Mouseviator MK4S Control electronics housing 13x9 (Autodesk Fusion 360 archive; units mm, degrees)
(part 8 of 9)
sketch "Sketch1" plane through (0, 0, 5) normal (0, 0, 1) x axis (-1, 0, 0)
  line L1 (-98.9644, -53.9879) -> (-98.9644, -59.9879)
  line L2 (-92.9644, -53.9879) -> (-98.9644, -53.9879)
  line L3 (-92.9644, -59.9879) -> (-92.9644, -53.9879)
  line L4 (-98.9644, -59.9879) -> (-92.9644, -59.9879)
  line L5 (-12.9644, 60.0121) -> (-12.9644, 66.0121)
  line L6 (-18.9644, 60.0121) -> (-12.9644, 60.0121)
  line L7 (-18.9644, 66.0121) -> (-18.9644, 60.0121)
  line L8 (-12.9644, 66.0121) -> (-18.9644, 66.0121)
  line L9 (-45.9644, -51.9879) -> (-20.9644, -51.9879)
  line L10 (-40.9644, -54.9879) -> (-45.9644, -51.9879)
  line L11 (-70.9644, -54.9879) -> (-40.9644, -54.9879)
  line L12 (-65.9644, -51.9879) -> (-70.9644, -54.9879)
  line L13 (-90.9644, -51.9879) -> (-65.9644, -51.9879)
  line L14 (-90.9644, -6.9879) -> (-90.9644, -51.9879)
  line L15 (-93.9644, -11.9879) -> (-90.9644, -6.9879)
  line L16 (-93.9644, 18.0121) -> (-93.9644, -11.9879)
  line L17 (-90.9644, 13.0121) -> (-93.9644, 18.0121)
  line L18 (-90.9644, 58.0121) -> (-90.9644, 13.0121)
  line L19 (-65.9644, 58.0121) -> (-90.9644, 58.0121)
  line L20 (-70.9644, 61.0121) -> (-65.9644, 58.0121)
  line L21 (-40.9644, 61.0121) -> (-70.9644, 61.0121)
  line L22 (-45.9644, 58.0121) -> (-40.9644, 61.0121)
  line L23 (-20.9644, 58.0121) -> (-45.9644, 58.0121)
  line L24 (-20.9644, 13.0121) -> (-20.9644, 58.0121)
  line L25 (-17.9644, 18.0121) -> (-20.9644, 13.0121)
  line L26 (-17.9644, -11.9879) -> (-17.9644, 18.0121)
  line L27 (-20.9644, -6.9879) -> (-17.9644, -11.9879)
  line L28 (-20.9644, -51.9879) -> (-20.9644, -6.9879)
  line L29 (-12.9644, -53.9879) -> (-18.9644, -53.9879)
  line L30 (-12.9644, -59.9879) -> (-12.9644, -53.9879)
  line L31 (-18.9644, -59.9879) -> (-12.9644, -59.9879)
  line L32 (-18.9644, -53.9879) -> (-18.9644, -59.9879)
  line L33 (-98.9644, 60.0121) -> (-92.9644, 60.0121)
  line L34 (-98.9644, 66.0121) -> (-98.9644, 60.0121)
  line L35 (-92.9644, 66.0121) -> (-98.9644, 66.0121)
  line L36 (-92.9644, 60.0121) -> (-92.9644, 66.0121)
  line L37 (-10.9644, -6.9879) -> (-10.9644, -61.9879)
  line L38 (-13.9644, -11.9879) -> (-10.9644, -6.9879)
  line L39 (-13.9644, 18.0121) -> (-13.9644, -11.9879)
  line L40 (-10.9644, 13.0121) -> (-13.9644, 18.0121)
  line L41 (-10.9644, 68.0121) -> (-10.9644, 13.0121)
  line L42 (-45.9644, 68.0121) -> (-10.9644, 68.0121)
  line L43 (-40.9644, 65.0121) -> (-45.9644, 68.0121)
  line L44 (-70.9644, 65.0121) -> (-40.9644, 65.0121)
  line L45 (-65.9644, 68.0121) -> (-70.9644, 65.0121)
  line L46 (-100.9644, 68.0121) -> (-65.9644, 68.0121)
  line L47 (-100.9644, 13.0121) -> (-100.9644, 68.0121)
  line L48 (-97.9644, 18.0121) -> (-100.9644, 13.0121)
  line L49 (-97.9644, -11.9879) -> (-97.9644, 18.0121)
  line L50 (-100.9644, -6.9879) -> (-97.9644, -11.9879)
  line L51 (-100.9644, -61.9879) -> (-100.9644, -6.9879)
  line L52 (-65.9644, -61.9879) -> (-100.9644, -61.9879)
  line L53 (-70.9644, -58.9879) -> (-65.9644, -61.9879)
  line L54 (-40.9644, -58.9879) -> (-70.9644, -58.9879)
  line L55 (-45.9644, -61.9879) -> (-40.9644, -58.9879)
  line L56 (-10.9644, -61.9879) -> (-45.9644, -61.9879)
  line L57 (-100.9644, -61.9879) -> (-10.9644, -61.9879)
  line L58 (-99.9644, -60.9879) -> (-100.9644, -61.9879)
  line L59 (-91.9644, -60.9879) -> (-99.9644, -60.9879)
  line L60 (-91.9644, -59.9879) -> (-91.9644, -60.9879)
  line L61 (-19.9644, -59.9879) -> (-91.9644, -59.9879)
  line L62 (-19.9644, -60.9879) -> (-19.9644, -59.9879)
  line L63 (-11.9644, -60.9879) -> (-19.9644, -60.9879)
  line L64 (-10.9644, -61.9879) -> (-11.9644, -60.9879)
  line L65 (-99.9437, -61.0379) -> (-100.8937, -61.9879)
  line L66 (-91.9144, -61.0379) -> (-99.9437, -61.0379)
  line L67 (-91.9144, -60.0379) -> (-91.9144, -61.0379)
  line L68 (-20.0144, -60.0379) -> (-91.9144, -60.0379)
  line L69 (-20.0144, -61.0379) -> (-20.0144, -60.0379)
  line L70 (-11.9851, -61.0379) -> (-20.0144, -61.0379)
  line L71 (-11.0351, -61.9879) -> (-11.9851, -61.0379)
  circle C1 centre (-24.4644, 61.5121) radius 1.7
  circle C2 centre (-93.9644, 54.5121) radius 1.7
  circle C3 centre (-87.4644, -55.4879) radius 1.7
  circle C4 centre (-17.4644, -48.4879) radius 1.7
  circle C5 centre (-24.4644, -55.4879) radius 1.7
  circle C6 centre (-93.9644, -48.4879) radius 1.7
  circle C7 centre (-87.4644, 61.5121) radius 1.7
  circle C8 centre (-17.4644, 54.5121) radius 1.7
  point P46 (-10.9644, -61.9879)
  point P74 (-10.9644, -61.9879)
  point P61 (-100.9644, -61.9879)
  point P76 (-100.9644, -61.9879)
  point P68 (-99.9644, -60.9879)
  point P77 (-99.9644, -60.9879)
  point P69 (-91.9644, -60.9879)
  point P78 (-91.9644, -60.9879)
  point P70 (-91.9644, -59.9879)
  point P79 (-91.9644, -59.9879)
  point P71 (-19.9644, -59.9879)
  point P80 (-19.9644, -59.9879)
  point P72 (-19.9644, -60.9879)
  point P81 (-19.9644, -60.9879)
  point P73 (-11.9644, -60.9879)
  point P82 (-11.9644, -60.9879)
  point P89 (-11.0351, -61.9879)
  point P90 (-100.8937, -61.9879)
  point P75 (-100.9644, -61.9879)
  coincident P46 P74
  coincident P61 P76
  coincident P68 P77
  coincident P69 P78
  coincident P70 P79
  coincident P71 P80
  coincident P72 P81
  coincident P73 P82
  coincident L56 P89
  coincident L52 P90
  dimension "d228_4_1" distance L57 L70 = 0.95 (= "side_wall_thick1_3")
  dimension "d229_4_1" distance L57 L68 = 1.95 (= "side_wall_thick2_3")
  dimension "d230_4_1" distance L57 L66 = 0.95 (= "side_wall_thick1_3")
  dimension "d231_4_1" distance P74 P75 = 90 (= "plate_height_3")
  dimension "d232_4_1" distance L64 L71 = 0.05 (= "wall_clearance_3")
  dimension "d233_4_1" distance L58 L65 = 0.05 (= "wall_clearance_3")
  dimension "d234_4_1" angle L57 L58 = 45 (= "wall_rorner_angle_6")
  dimension "d235_4_1" distance P74 L69 = 9.05 (= "side_wall_col_length_3")
  dimension "d244_4_1" distance P75 L67 = 9.05 (= "side_wall_col_length_3")
extrude "Extrude1" new body sketch "Sketch1" profile of L52 L53 L55 L56 blind 69.9 (= "column_height_3 - ( 2 * wall_clearance_3 )") named "d217_4_1" from offset 0.05 (= "wall_clearance_3") named "d216_4_1"
sketch "Sketch2" plane through (0, 61.9879, 0) normal (0, 1, 0) x axis (-1, 0, 0)
  line L1 (-11.0351, 74.95) -> (-100.8937, 74.95)
  line L2 (-100.8937, 74.95) -> (-100.8937, 5.05)
  line L3 (-11.0351, 74.95) -> (-11.0351, 5.05)
  line L4 (-11.0351, 5.05) -> (-100.8937, 5.05)
  line L5 (-11.0351, 74.95) -> (-11.0351, 5.05)
  line L6 (-100.8937, 74.95) -> (-11.0351, 74.95)
  line L7 (-100.8937, 5.05) -> (-100.8937, 74.95)
  line L8 (-90.8937, 64.95) -> (-21.0351, 64.95)
  line L9 (-90.8937, 15.05) -> (-90.8937, 64.95)
  line L10 (-21.0351, 15.05) -> (-90.8937, 15.05)
  line L11 (-21.0351, 64.95) -> (-21.0351, 15.05)
  circle C1 centre (-95.9644, 60) radius 1.7
  circle C2 centre (-95.9644, 20) radius 1.7
  circle C3 centre (-15.9644, 20) radius 1.7
  circle C4 centre (-15.9644, 60) radius 1.7
  dimension "d227_4_1" = -10 (= "-plate_square_thick_3")
hole "Hole1" HoleDepth 4 named "d220_1_1" HoleDiameter 3.4 named "d221_1_1" TipAngle 118 named "d222_1_1"
sketch "Sketch3" plane through (0, 61.9879, 0) normal (0, 1, 0) x axis (-1, 0, 0)
  line L1 (-11.0351, 5.05) -> (-100.8937, 5.05)
  line L2 (-11.0351, 74.95) -> (-11.0351, 5.05)
  line L3 (-100.8937, 74.95) -> (-11.0351, 74.95)
  line L4 (-100.8937, 5.05) -> (-100.8937, 74.95)
  line L5 (-55.9644, -6.6527) -> (-55.9644, 156.5527)
  line L6 (83.5909, 40) -> (-105.6612, 40)
  line L7 (-100.8937, 64.95) -> (-100.8937, 74.95)
  line L8 (-94.8937, 74.95) -> (-100.8937, 74.95)
  line L9 (-94.8937, 59.95) -> (-94.8937, 74.95)
  line L10 (-100.8937, 64.95) -> (-94.8937, 59.95)
  line L11 (-100.9437, 64.9735) -> (-106.8437, 60)
  line L12 (-106.8437, 60) -> (-106.8437, 74.9)
  line L13 (-100.8937, 64.9735) -> (-100.9437, 64.9735)
  line L14 (-100.8937, 74.9) -> (-106.8437, 74.9)
  line L15 (-100.8937, 5.1) -> (-106.8437, 5.1)
  line L16 (-106.8437, 20) -> (-106.8437, 5.1)
  line L17 (-100.9437, 15.0265) -> (-106.8437, 20)
  line L18 (-100.8937, 15.0265) -> (-100.9437, 15.0265)
  line L19 (-100.8937, 15.05) -> (-100.8937, 5.05)
  line L20 (-94.8937, 5.05) -> (-100.8937, 5.05)
  line L21 (-94.8937, 20.05) -> (-94.8937, 5.05)
  line L22 (-100.8937, 15.05) -> (-94.8937, 20.05)
  line L23 (-11.0351, 5.1) -> (-5.0851, 5.1)
  line L24 (-5.0851, 20) -> (-5.0851, 5.1)
  line L25 (-10.9851, 15.0265) -> (-5.0851, 20)
  line L26 (-11.0351, 15.0265) -> (-10.9851, 15.0265)
  line L27 (-11.0351, 15.05) -> (-11.0351, 5.05)
  line L28 (-17.0351, 5.05) -> (-11.0351, 5.05)
  line L29 (-17.0351, 20.05) -> (-17.0351, 5.05)
  line L30 (-11.0351, 15.05) -> (-17.0351, 20.05)
  line L31 (-11.0351, 74.9) -> (-5.0851, 74.9)
  line L32 (-5.0851, 60) -> (-5.0851, 74.9)
  line L33 (-11.0351, 64.9735) -> (-10.9851, 64.9735)
  line L34 (-10.9851, 64.9735) -> (-5.0851, 60)
  line L35 (-11.0351, 64.95) -> (-11.0351, 74.95)
  line L36 (-17.0351, 74.95) -> (-11.0351, 74.95)
  line L37 (-17.0351, 59.95) -> (-17.0351, 74.95)
  line L38 (-11.0351, 64.95) -> (-17.0351, 59.95)
  point P17 (-100.8937, 64.9735)
  point P18 (-100.8937, 74.9)
  point P10 (-100.8937, 74.95)
  point P24 (-100.8937, 5.05)
  point P11 (-100.8937, 64.95)
  point P25 (-100.8937, 15.05)
  point P12 (-94.8937, 74.95)
  point P26 (-94.8937, 5.05)
  point P13 (-94.8937, 59.95)
  point P27 (-94.8937, 20.05)
  point P14 (-100.9437, 64.9735)
  point P22 (-100.9437, 15.0265)
  point P15 (-106.8437, 60)
  point P21 (-106.8437, 20)
  point P16 (-106.8437, 74.9)
  point P19 (-106.8437, 5.1)
  point P23 (-100.8937, 15.0265)
  point P20 (-100.8937, 5.1)
  point P42 (-11.0351, 74.95)
  point P43 (-11.0351, 64.95)
  point P44 (-17.0351, 74.95)
  point P45 (-17.0351, 59.95)
  point P40 (-10.9851, 64.9735)
  point P39 (-5.0851, 60)
  point P37 (-5.0851, 74.9)
  point P41 (-11.0351, 64.9735)
  point P38 (-11.0351, 74.9)
  point P28 (-5.0851, 5.1)
  point P29 (-11.0351, 5.1)
  point P30 (-5.0851, 20)
  point P31 (-10.9851, 15.0265)
  point P32 (-11.0351, 15.0265)
  point P33 (-11.0351, 5.05)
  point P34 (-11.0351, 15.05)
  point P35 (-17.0351, 5.05)
  point P36 (-17.0351, 20.05)
  vertical L5
  horizontal L6
  midpoint L3 L5
  midpoint L2 L6
  coincident L7 P17
  coincident L4 P17
  perpendicular L7 L14
  coincident L4 P18
  symmetric L6 P10 P24
  symmetric L6 P11 P25
  symmetric L6 P12 P26
  symmetric L6 P13 P27
  symmetric L6 P14 P22
  symmetric L6 P15 P21
  symmetric L6 P16 P19
  symmetric L6 P17 P23
  symmetric L6 P18 P20
  symmetric L5 P10 P42
  symmetric L5 P11 P43
  symmetric L5 P12 P44
  symmetric L5 P13 P45
  symmetric L5 P14 P40
  symmetric L5 P15 P39
  symmetric L5 P16 P37
  symmetric L5 P17 P41
  symmetric L5 P18 P38
  symmetric L5 P19 P28
  symmetric L5 P20 P29
  symmetric L5 P21 P30
  symmetric L5 P22 P31
  symmetric L5 P23 P32
  symmetric L5 P24 P33
  symmetric L5 P25 P34
  symmetric L5 P26 P35
  symmetric L5 P27 P36
  dimension "d332_4_1" distance P12 P13 = 15 (= "join_width2_3")
  dimension "d333_4_1" distance P10 P12 = 6 (= "join_depth_3 * 2")
  dimension "d334_4_1" distance P10 P11 = 10 (= "join_width1_3")
  dimension "d336_4_1" distance P15 P16 = 14.9 (= "join_width2_3 - ( 2 * wall_clearance_3 )")
  dimension "d337_4_1" distance P16 P18 = 5.95 (= "join_depth_3 * 2 - wall_clearance_3")
  dimension "d338_4_1" distance P14 P17 = 0.05 (= "wall_clearance_3")
position "Position32"
sketch "uno doors hole" plane through (0, 61.9879, 0) normal (0, 1, 0) x axis (-1, 0, 0)
  line L1 (-28.8337, 29.05) -> (-79.8337, 29.05)
  line L2 (-28.8337, 8.05) -> (-28.8337, 29.05)
  line L3 (-79.8337, 8.05) -> (-28.8337, 8.05)
  line L4 (-79.8337, 29.05) -> (-79.8337, 8.05)
  line L5 (-100.8937, 5.05) -> (-100.8937, 74.95)
  line L6 (-11.0351, 5.05) -> (-100.8937, 5.05)
  line L7 (-11.0351, 74.95) -> (-11.0351, 5.05)
  line L8 (-100.8937, 74.95) -> (-11.0351, 74.95)
  line L9 (-28.8337, 8.05) -> (-79.8337, 8.05)
  line L10 (-79.8337, 5.05) -> (-28.8337, 5.05)
  line L11 (-84.8337, 29.05) -> (-79.8337, 29.05)
  line L12 (-84.8337, 5.05) -> (-84.8337, 29.05)
  line L13 (-79.8337, 5.05) -> (-84.8337, 5.05)
  line L14 (-79.8337, 29.05) -> (-79.8337, 8.05)
  line L15 (-23.8337, 29.05) -> (-28.8337, 29.05)
  line L16 (-23.8337, 5.05) -> (-23.8337, 29.05)
  line L17 (-28.8337, 5.05) -> (-23.8337, 5.05)
  line L18 (-28.8337, 29.05) -> (-28.8337, 8.05)
  line L19 (-82.3337, 5) -> (-82.3337, 29.05)
  line L20 (-26.3337, 5.05) -> (-26.3337, 29.05)
  line L21 (-82.3337, 8.05) -> (-79.8337, 8.05)
  line L22 (-26.3337, 8.05) -> (-28.8337, 8.05)
  line L23 (-79.8337, 5.05) -> (-79.8337, 8.05)
  line L24 (-28.8337, 5.05) -> (-28.8337, 8.05)
  point P11 (-28.8337, 5.05)
  point P19 (-82.3337, 29.05)
  point P21 (-26.3337, 29.05)
  point P22 (-26.3337, 5.05)
  point P23 (-82.3337, 8.05)
  point P24 (-26.3337, 8.05)
  point P2 (-79.8337, 29.05)
  point P3 (-28.8337, 29.05)
  point P4 (-28.8337, 8.05)
  point P13 (-84.8337, 29.05)
  point P16 (-23.8337, 29.05)
  horizontal L1
  vertical L2
  horizontal L3
  vertical L4
  horizontal L9
  horizontal L10
  coincident L6 P11
  horizontal L11
  vertical L12
  horizontal L13
  vertical L14
  horizontal L15
  vertical L16
  horizontal L17
  vertical L18
  midpoint L11 P19
  perpendicular L11 L19
  midpoint L15 P21
  midpoint L17 P22
  coincident L19 P23
  perpendicular L19 L21
  coincident L20 P24
  perpendicular L20 L22
  perpendicular L6 L23
  perpendicular L6 L24
  dimension "uno_doors_width_1" distance P2 P3 = 51
  dimension "uno_doors_height_1" distance P3 P4 = 21
  dimension "d539_1" distance L3 L6 = 3
  dimension "d540_1" distance L4 L5 = 21.06 (= "( 90 mm - uno_doors_width_1 ) * 0.54")
  dimension "uno_door_rails_width_1" distance P2 P13 = 5
  dimension "d542_1" distance P3 P16 = 5 (= "uno_door_rails_width_1")
extrude "Extrude3" cut sketch "uno doors hole" profile of L1 L2 L3 L4 L9 L14 L18 against normal blind 3 named "d543_1"
extrude "Extrude4" add sketch "uno doors hole" profile of L3 L6 L9 L10 L11 L12 L13 L15 L16 L17 L19 L20 L21 L22 along normal blind 2 (= "uno_doors_thick_1") named "d547_1"
extrude "Extrude5" add sketch "uno doors hole" profile of L2 L4 L6 L11 L12 L13 L14 L15 L16 L17 L18 L19 L20 L21 L22 L23 L24 blind 2 (= "uno_doors_thick_1") named "d550_1" from offset 2 (= "uno_doors_thick_1") named "d549_1"
extrude "Extrude6" add of existing geometry blind 29.4 (= "uno_doors_height_1 * 1.4") named "d552_1"
sketch "Sketch5" plane through (0, 61.9879, 0) normal (0, 1, 0) x axis (-1, 0, 0)
  line L1 (-79.7337, 5.05) -> (-79.7337, 8.05)
  line L2 (-28.9337, 5.05) -> (-28.9337, 8.05)
  line L3 (-28.9337, 8.05) -> (-79.7337, 8.05)
  line L4 (-79.7337, 5.05) -> (-28.9337, 5.05)
  line L5 (-26.3337, 5.05) -> (-26.3337, 29.05)
  line L6 (-82.3337, 5) -> (-82.3337, 29.05)
  line L7 (-82.3337, 8.05) -> (-79.7337, 8.05)
  line L8 (-26.4337, 29.05) -> (-82.2337, 29.05)
  line L9 (-82.2337, 5.05) -> (-26.4337, 5.05)
  line L10 (-82.3337, 8.05) -> (-82.3337, 5.05)
  line L11 (-26.4337, 5.05) -> (-26.4337, 29.05)
  line L12 (-82.2337, 29.05) -> (-82.2337, 5.05)
  line L13 (-26.4337, 29.05) -> (-82.2337, 29.05)
  line L14 (-26.4337, 34.05) -> (-26.4337, 29.05)
  line L15 (-82.2337, 34.05) -> (-26.4337, 34.05)
  line L16 (-82.2337, 29.05) -> (-82.2337, 34.05)
  line L17 (-79.7337, 34.05) -> (-79.7337, 8.05)
  line L18 (-28.9337, 34.05) -> (-28.9337, 8.05)
  line L19 (-26.4337, 8.05) -> (-28.9337, 8.05)
  line L20 (-28.9337, 12.05) -> (-79.7337, 12.05)
  point P12 (-82.3337, 8.05)
  point P22 (-28.9337, 34.05)
  point P23 (-26.4337, 8.05)
  point P24 (-79.7337, 12.05)
  point P25 (-28.9337, 12.05)
  point P21 (-79.7337, 34.05)
  point P17 (-82.2337, 29.05)
  point P20 (-82.2337, 34.05)
  perpendicular L2 L3
  perpendicular L1 L4
  coincident L6 P12
  perpendicular L6 L7
  horizontal L8
  horizontal L9
  vertical L10
  horizontal L13
  vertical L14
  horizontal L15
  vertical L16
  perpendicular L13 L17
  coincident L15 P22
  perpendicular L15 L18
  coincident L11 P23
  perpendicular L11 L19
  coincident L17 P24
  coincident L18 P25
  perpendicular L18 L20
  coincident L15 P21
  dimension "d559_1" distance P17 P20 = 5
  dimension "d563_1" distance L3 L20 = 4
extrude "Extrude7" new body sketch "Sketch5" profile of L3 L7 L8 L11 L12 L13 L14 L15 L16 L17 L18 L19 blind 1.9 (= "uno_doors_thick_1 - uno_doors_clearance_1") named "d561_1" from offset 0.1 (= "uno_doors_clearance_1") named "d560_1" bodies "uno_doors"
extrude "Extrude8" add sketch "Sketch5" profile of L3 L17 L18 L20 blind 0.1 (= "uno_doors_clearance_1") named "d565_1" from offset 2 (= "uno_doors_thick_1") named "d564_1"
extrude "Extrude9" add sketch "Sketch5" profile of L1 L2 L3 L4 L9 L17 L18 L20 blind 1.9 (= "uno_doors_thick_1 - uno_doors_clearance_1") named "d568_1" from offset 2.1 (= "uno_doors_thick_1 + uno_doors_clearance_1") named "d567_1"
extrude "Extrude10" add sketch "Sketch5" profile of L8 L13 L15 L17 L18 blind 2.2 (= "uno_doors_thick_1 + ( 2 * uno_doors_clearance_1 )") named "d571_1" from offset 2 (= "uno_doors_thick_1") named "d570_1"
extrude "Extrude11" add sketch "Sketch5" profile of L8 L13 L14 L15 L16 L17 L18 blind 2 (= "uno_doors_thick_1") named "d574_1" from offset 4.2 (= "uno_doors_thick_1 * 2 + ( 2 * uno_doors_clearance_1 )") named "d573_1"
fillet "Fillet1" radius 2 (= "uno_doors_thick_1") named "d577_1"
fillet "Fillet2" radius 1.2 (= "uno_doors_thick_1 * 0.6") named "d579_1"
sketch "Sketch1" plane through (0, 0, 5) normal (0, 0, 1) x axis (-1, 0, 0)
  line L1 (-98.9644, -53.9879) -> (-98.9644, -59.9879)
  line L2 (-92.9644, -53.9879) -> (-98.9644, -53.9879)
  line L3 (-92.9644, -59.9879) -> (-92.9644, -53.9879)
  line L4 (-98.9644, -59.9879) -> (-92.9644, -59.9879)
  line L5 (-12.9644, 60.0121) -> (-12.9644, 66.0121)
  line L6 (-18.9644, 60.0121) -> (-12.9644, 60.0121)
  line L7 (-18.9644, 66.0121) -> (-18.9644, 60.0121)
  line L8 (-12.9644, 66.0121) -> (-18.9644, 66.0121)
  line L9 (-45.9644, -51.9879) -> (-20.9644, -51.9879)
  line L10 (-40.9644, -54.9879) -> (-45.9644, -51.9879)
  line L11 (-70.9644, -54.9879) -> (-40.9644, -54.9879)
  line L12 (-65.9644, -51.9879) -> (-70.9644, -54.9879)
  line L13 (-90.9644, -51.9879) -> (-65.9644, -51.9879)
  line L14 (-90.9644, -6.9879) -> (-90.9644, -51.9879)
  line L15 (-93.9644, -11.9879) -> (-90.9644, -6.9879)
  line L16 (-93.9644, 18.0121) -> (-93.9644, -11.9879)
  line L17 (-90.9644, 13.0121) -> (-93.9644, 18.0121)
  line L18 (-90.9644, 58.0121) -> (-90.9644, 13.0121)
  line L19 (-65.9644, 58.0121) -> (-90.9644, 58.0121)
  line L20 (-70.9644, 61.0121) -> (-65.9644, 58.0121)
  line L21 (-40.9644, 61.0121) -> (-70.9644, 61.0121)
  line L22 (-45.9644, 58.0121) -> (-40.9644, 61.0121)
  line L23 (-20.9644, 58.0121) -> (-45.9644, 58.0121)
  line L24 (-20.9644, 13.0121) -> (-20.9644, 58.0121)
  line L25 (-17.9644, 18.0121) -> (-20.9644, 13.0121)
  line L26 (-17.9644, -11.9879) -> (-17.9644, 18.0121)
  line L27 (-20.9644, -6.9879) -> (-17.9644, -11.9879)
  line L28 (-20.9644, -51.9879) -> (-20.9644, -6.9879)
  line L29 (-12.9644, -53.9879) -> (-18.9644, -53.9879)
  line L30 (-12.9644, -59.9879) -> (-12.9644, -53.9879)
  line L31 (-18.9644, -59.9879) -> (-12.9644, -59.9879)
  line L32 (-18.9644, -53.9879) -> (-18.9644, -59.9879)
  line L33 (-98.9644, 60.0121) -> (-92.9644, 60.0121)
  line L34 (-98.9644, 66.0121) -> (-98.9644, 60.0121)
  line L35 (-92.9644, 66.0121) -> (-98.9644, 66.0121)
  line L36 (-92.9644, 60.0121) -> (-92.9644, 66.0121)
  line L37 (-10.9644, -6.9879) -> (-10.9644, -61.9879)
  line L38 (-13.9644, -11.9879) -> (-10.9644, -6.9879)
  line L39 (-13.9644, 18.0121) -> (-13.9644, -11.9879)
  line L40 (-10.9644, 13.0121) -> (-13.9644, 18.0121)
  line L41 (-10.9644, 68.0121) -> (-10.9644, 13.0121)
  line L42 (-45.9644, 68.0121) -> (-10.9644, 68.0121)
  line L43 (-40.9644, 65.0121) -> (-45.9644, 68.0121)
  line L44 (-70.9644, 65.0121) -> (-40.9644, 65.0121)
  line L45 (-65.9644, 68.0121) -> (-70.9644, 65.0121)
  line L46 (-100.9644, 68.0121) -> (-65.9644, 68.0121)
  line L47 (-100.9644, 13.0121) -> (-100.9644, 68.0121)
  line L48 (-97.9644, 18.0121) -> (-100.9644, 13.0121)
  line L49 (-97.9644, -11.9879) -> (-97.9644, 18.0121)
  line L50 (-100.9644, -6.9879) -> (-97.9644, -11.9879)
  line L51 (-100.9644, -61.9879) -> (-100.9644, -6.9879)
  line L52 (-65.9644, -61.9879) -> (-100.9644, -61.9879)
  line L53 (-70.9644, -58.9879) -> (-65.9644, -61.9879)
  line L54 (-40.9644, -58.9879) -> (-70.9644, -58.9879)
  line L55 (-45.9644, -61.9879) -> (-40.9644, -58.9879)
  line L56 (-10.9644, -61.9879) -> (-45.9644, -61.9879)
  line L57 (-100.9644, -61.9879) -> (-10.9644, -61.9879)
  line L58 (-99.9644, -60.9879) -> (-100.9644, -61.9879)
  line L59 (-91.9644, -60.9879) -> (-99.9644, -60.9879)
  line L60 (-91.9644, -59.9879) -> (-91.9644, -60.9879)
  line L61 (-19.9644, -59.9879) -> (-91.9644, -59.9879)
  line L62 (-19.9644, -60.9879) -> (-19.9644, -59.9879)
  line L63 (-11.9644, -60.9879) -> (-19.9644, -60.9879)
  line L64 (-10.9644, -61.9879) -> (-11.9644, -60.9879)
  line L65 (-99.9437, -61.0379) -> (-100.8937, -61.9879)
  line L66 (-91.9144, -61.0379) -> (-99.9437, -61.0379)
  line L67 (-91.9144, -60.0379) -> (-91.9144, -61.0379)
  line L68 (-20.0144, -60.0379) -> (-91.9144, -60.0379)
  line L69 (-20.0144, -61.0379) -> (-20.0144, -60.0379)
  line L70 (-11.9851, -61.0379) -> (-20.0144, -61.0379)
  line L71 (-11.0351, -61.9879) -> (-11.9851, -61.0379)
  circle C1 centre (-24.4644, 61.5121) radius 1.7
  circle C2 centre (-93.9644, 54.5121) radius 1.7
  circle C3 centre (-87.4644, -55.4879) radius 1.7
  circle C4 centre (-17.4644, -48.4879) radius 1.7
  circle C5 centre (-24.4644, -55.4879) radius 1.7
  circle C6 centre (-93.9644, -48.4879) radius 1.7
  circle C7 centre (-87.4644, 61.5121) radius 1.7
  circle C8 centre (-17.4644, 54.5121) radius 1.7
  point P46 (-10.9644, -61.9879)
  point P74 (-10.9644, -61.9879)
  point P61 (-100.9644, -61.9879)
  point P76 (-100.9644, -61.9879)
  point P68 (-99.9644, -60.9879)
  point P77 (-99.9644, -60.9879)
  point P69 (-91.9644, -60.9879)
  point P78 (-91.9644, -60.9879)
  point P70 (-91.9644, -59.9879)
  point P79 (-91.9644, -59.9879)
  point P71 (-19.9644, -59.9879)
  point P80 (-19.9644, -59.9879)
  point P72 (-19.9644, -60.9879)
  point P81 (-19.9644, -60.9879)
  point P73 (-11.9644, -60.9879)
  point P82 (-11.9644, -60.9879)
  point P89 (-11.0351, -61.9879)
  point P90 (-100.8937, -61.9879)
  point P75 (-100.9644, -61.9879)
  coincident P46 P74
  coincident P61 P76
  coincident P68 P77
  coincident P69 P78
  coincident P70 P79
  coincident P71 P80
  coincident P72 P81
  coincident P73 P82
  coincident L56 P89
  coincident L52 P90
  dimension "d228_3_2_1_1" distance L57 L70 = 0.95 (= "side_wall_thick1_4")
  dimension "d229_3_2_1_1" distance L57 L68 = 1.95 (= "side_wall_thick2_4")
  dimension "d230_3_2_1_1" distance L57 L66 = 0.95 (= "side_wall_thick1_4")
  dimension "d231_3_2_1_1" distance P74 P75 = 90 (= "plate_height_4")
  dimension "d232_3_2_1_1" distance L64 L71 = 0.05 (= "wall_clearance_4")
  dimension "d233_3_2_1_1" distance L58 L65 = 0.05 (= "wall_clearance_4")
  dimension "d234_3_2_1_1" angle L57 L58 = 45 (= "wall_rorner_angle_7")
  dimension "d235_3_2_1_1" distance P74 L69 = 9.05 (= "side_wall_col_length_4")
  dimension "d244_3_2_1_1" distance P75 L67 = 9.05 (= "side_wall_col_length_4")
extrude "Extrude1" new body sketch "Sketch1" profile of L52 L53 L55 L56 blind 69.9 (= "column_height_4 - ( 2 * wall_clearance_4 )") named "d217_3_2_1_1" from offset 0.05 (= "wall_clearance_4") named "d216_3_2_1_1"
sketch "Sketch2" plane through (0, 61.9879, 0) normal (0, 1, 0) x axis (-1, 0, 0)
  line L1 (-11.0351, 74.95) -> (-100.8937, 74.95)
  line L2 (-100.8937, 74.95) -> (-100.8937, 5.05)
  line L3 (-11.0351, 74.95) -> (-11.0351, 5.05)
  line L4 (-11.0351, 5.05) -> (-100.8937, 5.05)
  line L5 (-11.0351, 74.95) -> (-11.0351, 5.05)
  line L6 (-100.8937, 74.95) -> (-11.0351, 74.95)
  line L7 (-100.8937, 5.05) -> (-100.8937, 74.95)
  line L8 (-90.8937, 64.95) -> (-21.0351, 64.95)
  line L9 (-90.8937, 15.05) -> (-90.8937, 64.95)
  line L10 (-21.0351, 15.05) -> (-90.8937, 15.05)
  line L11 (-21.0351, 64.95) -> (-21.0351, 15.05)
  circle C1 centre (-95.9644, 60) radius 1.7
  circle C2 centre (-95.9644, 20) radius 1.7
  circle C3 centre (-15.9644, 20) radius 1.7
  circle C4 centre (-15.9644, 60) radius 1.7
  dimension "d227_3_2_1_1" = -10 (= "-plate_square_thick_4")
hole "Hole1" HoleDepth 4 named "d220_3_2_1_1" HoleDiameter 3.4 named "d221_3_2_1_1" TipAngle 118 named "d222_3_2_1_1"
sketch "Sketch3" plane through (0, 61.9879, 0) normal (0, 1, 0) x axis (-1, 0, 0)
  line L1 (-11.0351, 5.05) -> (-100.8937, 5.05)
  line L2 (-11.0351, 74.95) -> (-11.0351, 5.05)
  line L3 (-100.8937, 74.95) -> (-11.0351, 74.95)
  line L4 (-100.8937, 5.05) -> (-100.8937, 74.95)
  line L5 (-55.9644, -6.6527) -> (-55.9644, 156.5527)
  line L6 (83.5909, 40) -> (-105.6612, 40)
  line L7 (-100.8937, 64.95) -> (-100.8937, 74.95)
  line L8 (-94.8937, 74.95) -> (-100.8937, 74.95)
  line L9 (-94.8937, 59.95) -> (-94.8937, 74.95)
  line L10 (-100.8937, 64.95) -> (-94.8937, 59.95)
  line L11 (-100.9437, 64.9735) -> (-106.8437, 60)
  line L12 (-106.8437, 60) -> (-106.8437, 74.9)
  line L13 (-100.8937, 64.9735) -> (-100.9437, 64.9735)
  line L14 (-100.8937, 74.9) -> (-106.8437, 74.9)
  line L15 (-100.8937, 5.1) -> (-106.8437, 5.1)
  line L16 (-106.8437, 20) -> (-106.8437, 5.1)
  line L17 (-100.9437, 15.0265) -> (-106.8437, 20)
  line L18 (-100.8937, 15.0265) -> (-100.9437, 15.0265)
  line L19 (-100.8937, 15.05) -> (-100.8937, 5.05)
  line L20 (-94.8937, 5.05) -> (-100.8937, 5.05)
  line L21 (-94.8937, 20.05) -> (-94.8937, 5.05)
  line L22 (-100.8937, 15.05) -> (-94.8937, 20.05)
  line L23 (-11.0351, 5.1) -> (-5.0851, 5.1)
  line L24 (-5.0851, 20) -> (-5.0851, 5.1)
  line L25 (-10.9851, 15.0265) -> (-5.0851, 20)
  line L26 (-11.0351, 15.0265) -> (-10.9851, 15.0265)
  line L27 (-11.0351, 15.05) -> (-11.0351, 5.05)
  line L28 (-17.0351, 5.05) -> (-11.0351, 5.05)
  line L29 (-17.0351, 20.05) -> (-17.0351, 5.05)
  line L30 (-11.0351, 15.05) -> (-17.0351, 20.05)
  line L31 (-11.0351, 74.9) -> (-5.0851, 74.9)
  line L32 (-5.0851, 60) -> (-5.0851, 74.9)
  line L33 (-11.0351, 64.9735) -> (-10.9851, 64.9735)
  line L34 (-10.9851, 64.9735) -> (-5.0851, 60)
  line L35 (-11.0351, 64.95) -> (-11.0351, 74.95)
  line L36 (-17.0351, 74.95) -> (-11.0351, 74.95)
  line L37 (-17.0351, 59.95) -> (-17.0351, 74.95)
  line L38 (-11.0351, 64.95) -> (-17.0351, 59.95)
  point P17 (-100.8937, 64.9735)
  point P18 (-100.8937, 74.9)
  point P10 (-100.8937, 74.95)
  point P24 (-100.8937, 5.05)
  point P11 (-100.8937, 64.95)
  point P25 (-100.8937, 15.05)
  point P12 (-94.8937, 74.95)
  point P26 (-94.8937, 5.05)
  point P13 (-94.8937, 59.95)
  point P27 (-94.8937, 20.05)
  point P14 (-100.9437, 64.9735)
  point P22 (-100.9437, 15.0265)
  point P15 (-106.8437, 60)
  point P21 (-106.8437, 20)
  point P16 (-106.8437, 74.9)
  point P19 (-106.8437, 5.1)
  point P23 (-100.8937, 15.0265)
  point P20 (-100.8937, 5.1)
  point P42 (-11.0351, 74.95)
  point P43 (-11.0351, 64.95)
  point P44 (-17.0351, 74.95)
  point P45 (-17.0351, 59.95)
  point P40 (-10.9851, 64.9735)
  point P39 (-5.0851, 60)
  point P37 (-5.0851, 74.9)
  point P41 (-11.0351, 64.9735)
  point P38 (-11.0351, 74.9)
  point P28 (-5.0851, 5.1)
  point P29 (-11.0351, 5.1)
  point P30 (-5.0851, 20)
  point P31 (-10.9851, 15.0265)
  point P32 (-11.0351, 15.0265)
  point P33 (-11.0351, 5.05)
  point P34 (-11.0351, 15.05)
  point P35 (-17.0351, 5.05)
  point P36 (-17.0351, 20.05)
  vertical L5
  horizontal L6
  midpoint L3 L5
  midpoint L2 L6
  coincident L7 P17
  coincident L4 P17
  perpendicular L7 L14
  coincident L4 P18
  symmetric L6 P10 P24
  symmetric L6 P11 P25
  symmetric L6 P12 P26
  symmetric L6 P13 P27
  symmetric L6 P14 P22
  symmetric L6 P15 P21
  symmetric L6 P16 P19
  symmetric L6 P17 P23
  symmetric L6 P18 P20
  symmetric L5 P10 P42
  symmetric L5 P11 P43
  symmetric L5 P12 P44
  symmetric L5 P13 P45
  symmetric L5 P14 P40
  symmetric L5 P15 P39
  symmetric L5 P16 P37
  symmetric L5 P17 P41
  symmetric L5 P18 P38
  symmetric L5 P19 P28
  symmetric L5 P20 P29
  symmetric L5 P21 P30
  symmetric L5 P22 P31
  symmetric L5 P23 P32
  symmetric L5 P24 P33
  symmetric L5 P25 P34
  symmetric L5 P26 P35
  symmetric L5 P27 P36
  dimension "d332_3_2_1_1" distance P12 P13 = 15 (= "join_width2_4")
  dimension "d333_3_2_1_1" distance P10 P12 = 6 (= "join_depth_4 * 2")
  dimension "d334_3_2_1_1" distance P10 P11 = 10 (= "join_width1_4")
  dimension "d336_3_2_1_1" distance P15 P16 = 14.9 (= "join_width2_4 - ( 2 * wall_clearance_4 )")
  dimension "d337_3_2_1_1" distance P16 P18 = 5.95 (= "join_depth_4 * 2 - wall_clearance_4")
  dimension "d338_3_2_1_1" distance P14 P17 = 0.05 (= "wall_clearance_4")
position "Position33"
sketch "Sketch4" plane through (0, 61.9879, 0) normal (0, 1, 0) x axis (1, 0, 0)
  line L1 (11.0351, -5.05) -> (100.8937, -5.05)
  line L2 (11.0351, -74.95) -> (11.0351, -5.05)
  line L3 (100.8937, -74.95) -> (11.0351, -74.95)
  line L4 (100.8937, -5.05) -> (100.8937, -74.95)
  line L5 (45.9644, -5.05) -> (45.9644, -12.415)
  line L6 (35.9644, -5.05) -> (35.9644, -12.415)
  line L7 (65.9644, -5.05) -> (65.9644, -12.423)
  line L8 (75.967, -5.05) -> (75.9644, -12.4248)
  line L9 (55.9644, 6.6527) -> (55.9644, -156.5527)
  circle C1 centre (15.9644, -20) radius 1.7
  circle C2 centre (95.9644, -60) radius 1.7
  circle C3 centre (95.9644, -20) radius 1.7
  circle C4 centre (15.9644, -60) radius 1.7
  arc A1 centre (40.9644, -12.415) radius 5 clockwise from (45.9644, -12.415) to (35.9644, -12.415)
  arc A2 centre (70.9644, -12.423) radius 5 clockwise from (75.9644, -12.4248) to (65.9644, -12.423)
  point P12 (45.9644, -5.05)
  point P14 (35.9644, -5.05)
  coincident L1 P12
  tangent L5 A1
  coincident L1 P14
  tangent L6 A1
  perpendicular L1 L6
  tangent A2 L8
  tangent L7 A2
  dimension "cable_hole_d_2_1_1" diameter A1 = 10
  dimension "d534_1_1" diameter A2 = 10
  dimension "d535_1_1" distance L7 L9 = 10
  dimension "d536_1_1" distance L5 L9 = 10
extrude "Extrude4" cut sketch "Sketch4" profile of L1 L7 A2 L8 against normal blind 2 named "d517_2_1_1"
position "Position34"
component_insert "Component Insert2"
sketch "Sketch1" plane through (0, 0, 5) normal (0, 0, 1) x axis (-1, 0, 0)
  line L1 (-98.9644, -53.9879) -> (-98.9644, -59.9879)
  line L2 (-92.9644, -53.9879) -> (-98.9644, -53.9879)
  line L3 (-92.9644, -59.9879) -> (-92.9644, -53.9879)
  line L4 (-98.9644, -59.9879) -> (-92.9644, -59.9879)
  line L5 (-12.9644, 60.0121) -> (-12.9644, 66.0121)
  line L6 (-18.9644, 60.0121) -> (-12.9644, 60.0121)
  line L7 (-18.9644, 66.0121) -> (-18.9644, 60.0121)
  line L8 (-12.9644, 66.0121) -> (-18.9644, 66.0121)
  line L9 (-45.9644, -51.9879) -> (-20.9644, -51.9879)
  line L10 (-40.9644, -54.9879) -> (-45.9644, -51.9879)
  line L11 (-70.9644, -54.9879) -> (-40.9644, -54.9879)
  line L12 (-65.9644, -51.9879) -> (-70.9644, -54.9879)
  line L13 (-90.9644, -51.9879) -> (-65.9644, -51.9879)
  line L14 (-90.9644, -6.9879) -> (-90.9644, -51.9879)
  line L15 (-93.9644, -11.9879) -> (-90.9644, -6.9879)
  line L16 (-93.9644, 18.0121) -> (-93.9644, -11.9879)
  line L17 (-90.9644, 13.0121) -> (-93.9644, 18.0121)
  line L18 (-90.9644, 58.0121) -> (-90.9644, 13.0121)
  line L19 (-65.9644, 58.0121) -> (-90.9644, 58.0121)
  line L20 (-70.9644, 61.0121) -> (-65.9644, 58.0121)
  line L21 (-40.9644, 61.0121) -> (-70.9644, 61.0121)
  line L22 (-45.9644, 58.0121) -> (-40.9644, 61.0121)
  line L23 (-20.9644, 58.0121) -> (-45.9644, 58.0121)
  line L24 (-20.9644, 13.0121) -> (-20.9644, 58.0121)
  line L25 (-17.9644, 18.0121) -> (-20.9644, 13.0121)
  line L26 (-17.9644, -11.9879) -> (-17.9644, 18.0121)
  line L27 (-20.9644, -6.9879) -> (-17.9644, -11.9879)
  line L28 (-20.9644, -51.9879) -> (-20.9644, -6.9879)
  line L29 (-12.9644, -53.9879) -> (-18.9644, -53.9879)
  line L30 (-12.9644, -59.9879) -> (-12.9644, -53.9879)
  line L31 (-18.9644, -59.9879) -> (-12.9644, -59.9879)
  line L32 (-18.9644, -53.9879) -> (-18.9644, -59.9879)
  line L33 (-98.9644, 60.0121) -> (-92.9644, 60.0121)
  line L34 (-98.9644, 66.0121) -> (-98.9644, 60.0121)
  line L35 (-92.9644, 66.0121) -> (-98.9644, 66.0121)
  line L36 (-92.9644, 60.0121) -> (-92.9644, 66.0121)
  line L37 (-10.9644, -6.9879) -> (-10.9644, -61.9879)
  line L38 (-13.9644, -11.9879) -> (-10.9644, -6.9879)
  line L39 (-13.9644, 18.0121) -> (-13.9644, -11.9879)
  line L40 (-10.9644, 13.0121) -> (-13.9644, 18.0121)
  line L41 (-10.9644, 68.0121) -> (-10.9644, 13.0121)
  line L42 (-45.9644, 68.0121) -> (-10.9644, 68.0121)
  line L43 (-40.9644, 65.0121) -> (-45.9644, 68.0121)
  line L44 (-70.9644, 65.0121) -> (-40.9644, 65.0121)
  line L45 (-65.9644, 68.0121) -> (-70.9644, 65.0121)
  line L46 (-100.9644, 68.0121) -> (-65.9644, 68.0121)
  line L47 (-100.9644, 13.0121) -> (-100.9644, 68.0121)
  line L48 (-97.9644, 18.0121) -> (-100.9644, 13.0121)
  line L49 (-97.9644, -11.9879) -> (-97.9644, 18.0121)
  line L50 (-100.9644, -6.9879) -> (-97.9644, -11.9879)
  line L51 (-100.9644, -61.9879) -> (-100.9644, -6.9879)
  line L52 (-65.9644, -61.9879) -> (-100.9644, -61.9879)
  line L53 (-70.9644, -58.9879) -> (-65.9644, -61.9879)
  line L54 (-40.9644, -58.9879) -> (-70.9644, -58.9879)
  line L55 (-45.9644, -61.9879) -> (-40.9644, -58.9879)
  line L56 (-10.9644, -61.9879) -> (-45.9644, -61.9879)
  line L57 (-100.9644, -61.9879) -> (-10.9644, -61.9879)
  line L58 (-99.9644, -60.9879) -> (-100.9644, -61.9879)
  line L59 (-91.9644, -60.9879) -> (-99.9644, -60.9879)
  line L60 (-91.9644, -59.9879) -> (-91.9644, -60.9879)
  line L61 (-19.9644, -59.9879) -> (-91.9644, -59.9879)
  line L62 (-19.9644, -60.9879) -> (-19.9644, -59.9879)
  line L63 (-11.9644, -60.9879) -> (-19.9644, -60.9879)
  line L64 (-10.9644, -61.9879) -> (-11.9644, -60.9879)
  line L65 (-99.9437, -61.0379) -> (-100.8937, -61.9879)
  line L66 (-91.9144, -61.0379) -> (-99.9437, -61.0379)
  line L67 (-91.9144, -60.0379) -> (-91.9144, -61.0379)
  line L68 (-20.0144, -60.0379) -> (-91.9144, -60.0379)
  line L69 (-20.0144, -61.0379) -> (-20.0144, -60.0379)
  line L70 (-11.9851, -61.0379) -> (-20.0144, -61.0379)
  line L71 (-11.0351, -61.9879) -> (-11.9851, -61.0379)
  circle C1 centre (-24.4644, 61.5121) radius 1.7
  circle C2 centre (-93.9644, 54.5121) radius 1.7
  circle C3 centre (-87.4644, -55.4879) radius 1.7
  circle C4 centre (-17.4644, -48.4879) radius 1.7
  circle C5 centre (-24.4644, -55.4879) radius 1.7
  circle C6 centre (-93.9644, -48.4879) radius 1.7
  circle C7 centre (-87.4644, 61.5121) radius 1.7
  circle C8 centre (-17.4644, 54.5121) radius 1.7
  point P46 (-10.9644, -61.9879)
  point P74 (-10.9644, -61.9879)
  point P61 (-100.9644, -61.9879)
  point P76 (-100.9644, -61.9879)
  point P68 (-99.9644, -60.9879)
  point P77 (-99.9644, -60.9879)
  point P69 (-91.9644, -60.9879)
  point P78 (-91.9644, -60.9879)
  point P70 (-91.9644, -59.9879)
  point P79 (-91.9644, -59.9879)
  point P71 (-19.9644, -59.9879)
  point P80 (-19.9644, -59.9879)
  point P72 (-19.9644, -60.9879)
  point P81 (-19.9644, -60.9879)
  point P73 (-11.9644, -60.9879)
  point P82 (-11.9644, -60.9879)
  point P89 (-11.0351, -61.9879)
  point P90 (-100.8937, -61.9879)
  point P75 (-100.9644, -61.9879)
  coincident P46 P74
  coincident P61 P76
  coincident P68 P77
  coincident P69 P78
  coincident P70 P79
  coincident P71 P80
  coincident P72 P81
  coincident P73 P82
  coincident L56 P89
  coincident L52 P90
  dimension "d228_3_2" distance L57 L70 = 0.95 (= "side_wall_thick1")
  dimension "d229_3_2" distance L57 L68 = 1.95 (= "side_wall_thick2")
  dimension "d230_3_2" distance L57 L66 = 0.95 (= "side_wall_thick1")
  dimension "d231_3_2" distance P74 P75 = 90 (= "plate_height")
  dimension "d232_3_2" distance L64 L71 = 0.05 (= "wall_clearance")
  dimension "d233_3_2" distance L58 L65 = 0.05 (= "wall_clearance")
  dimension "d234_3_2" angle L57 L58 = 45 (= "wall_rorner_angle")
  dimension "d235_3_2" distance P74 L69 = 9.05 (= "side_wall_col_length")
  dimension "d244_3_2" distance P75 L67 = 9.05 (= "side_wall_col_length")
extrude "Extrude1" new body sketch "Sketch1" profile of L52 L53 L55 L56 blind 69.9 (= "column_height - ( 2 * wall_clearance )") named "d217_3_2" from offset 0.05 (= "wall_clearance") named "d216_3_2"
sketch "Sketch2" plane through (0, 61.9879, 0) normal (0, 1, 0) x axis (-1, 0, 0)
  line L1 (-11.0351, 74.95) -> (-100.8937, 74.95)
  line L2 (-100.8937, 74.95) -> (-100.8937, 5.05)
  line L3 (-11.0351, 74.95) -> (-11.0351, 5.05)
  line L4 (-11.0351, 5.05) -> (-100.8937, 5.05)
  line L5 (-11.0351, 74.95) -> (-11.0351, 5.05)
  line L6 (-100.8937, 74.95) -> (-11.0351, 74.95)
  line L7 (-100.8937, 5.05) -> (-100.8937, 74.95)
  line L8 (-90.8937, 64.95) -> (-21.0351, 64.95)
  line L9 (-90.8937, 15.05) -> (-90.8937, 64.95)
  line L10 (-21.0351, 15.05) -> (-90.8937, 15.05)
  line L11 (-21.0351, 64.95) -> (-21.0351, 15.05)
  circle C1 centre (-95.9644, 60) radius 1.7
  circle C2 centre (-95.9644, 20) radius 1.7
  circle C3 centre (-15.9644, 20) radius 1.7
  circle C4 centre (-15.9644, 60) radius 1.7
hole "Hole1" HoleDepth 4 named "d220_3_2" HoleDiameter 3.4 named "d221_3_2" TipAngle 118 named "d222_3_2"
sketch "Sketch3" plane through (0, 61.9879, 0) normal (0, 1, 0) x axis (-1, 0, 0)
  line L1 (-11.0351, 5.05) -> (-100.8937, 5.05)
  line L2 (-11.0351, 74.95) -> (-11.0351, 5.05)
  line L3 (-100.8937, 74.95) -> (-11.0351, 74.95)
  line L4 (-100.8937, 5.05) -> (-100.8937, 74.95)
  line L5 (-55.9644, -6.6527) -> (-55.9644, 156.5527)
  line L6 (83.5909, 40) -> (-105.6612, 40)
  line L7 (-100.8937, 64.95) -> (-100.8937, 74.95)
  line L8 (-94.8937, 74.95) -> (-100.8937, 74.95)
  line L9 (-94.8937, 59.95) -> (-94.8937, 74.95)
  line L10 (-100.8937, 64.95) -> (-94.8937, 59.95)
  line L11 (-100.9437, 64.9735) -> (-106.8437, 60)
  line L12 (-106.8437, 60) -> (-106.8437, 74.9)
  line L13 (-100.8937, 64.9735) -> (-100.9437, 64.9735)
  line L14 (-100.8937, 74.9) -> (-106.8437, 74.9)
  line L15 (-100.8937, 5.1) -> (-106.8437, 5.1)
  line L16 (-106.8437, 20) -> (-106.8437, 5.1)
  line L17 (-100.9437, 15.0265) -> (-106.8437, 20)
  line L18 (-100.8937, 15.0265) -> (-100.9437, 15.0265)
  line L19 (-100.8937, 15.05) -> (-100.8937, 5.05)
  line L20 (-94.8937, 5.05) -> (-100.8937, 5.05)
  line L21 (-94.8937, 20.05) -> (-94.8937, 5.05)
  line L22 (-100.8937, 15.05) -> (-94.8937, 20.05)
  line L23 (-11.0351, 5.1) -> (-5.0851, 5.1)
  line L24 (-5.0851, 20) -> (-5.0851, 5.1)
  line L25 (-10.9851, 15.0265) -> (-5.0851, 20)
  line L26 (-11.0351, 15.0265) -> (-10.9851, 15.0265)
  line L27 (-11.0351, 15.05) -> (-11.0351, 5.05)
  line L28 (-17.0351, 5.05) -> (-11.0351, 5.05)
  line L29 (-17.0351, 20.05) -> (-17.0351, 5.05)
  line L30 (-11.0351, 15.05) -> (-17.0351, 20.05)
  line L31 (-11.0351, 74.9) -> (-5.0851, 74.9)
  line L32 (-5.0851, 60) -> (-5.0851, 74.9)
  line L33 (-11.0351, 64.9735) -> (-10.9851, 64.9735)
  line L34 (-10.9851, 64.9735) -> (-5.0851, 60)
  line L35 (-11.0351, 64.95) -> (-11.0351, 74.95)
  line L36 (-17.0351, 74.95) -> (-11.0351, 74.95)
  line L37 (-17.0351, 59.95) -> (-17.0351, 74.95)
  line L38 (-11.0351, 64.95) -> (-17.0351, 59.95)
  point P17 (-100.8937, 64.9735)
  point P18 (-100.8937, 74.9)
  point P10 (-100.8937, 74.95)
  point P24 (-100.8937, 5.05)
  point P11 (-100.8937, 64.95)
  point P25 (-100.8937, 15.05)
  point P12 (-94.8937, 74.95)
  point P26 (-94.8937, 5.05)
  point P13 (-94.8937, 59.95)
  point P27 (-94.8937, 20.05)
  point P14 (-100.9437, 64.9735)
  point P22 (-100.9437, 15.0265)
  point P15 (-106.8437, 60)
  point P21 (-106.8437, 20)
  point P16 (-106.8437, 74.9)
  point P19 (-106.8437, 5.1)
  point P23 (-100.8937, 15.0265)
  point P20 (-100.8937, 5.1)
  point P42 (-11.0351, 74.95)
  point P43 (-11.0351, 64.95)
  point P44 (-17.0351, 74.95)
  point P45 (-17.0351, 59.95)
  point P40 (-10.9851, 64.9735)
  point P39 (-5.0851, 60)
  point P37 (-5.0851, 74.9)
  point P41 (-11.0351, 64.9735)
  point P38 (-11.0351, 74.9)
  point P28 (-5.0851, 5.1)
  point P29 (-11.0351, 5.1)
  point P30 (-5.0851, 20)
  point P31 (-10.9851, 15.0265)
  point P32 (-11.0351, 15.0265)
  point P33 (-11.0351, 5.05)
  point P34 (-11.0351, 15.05)
  point P35 (-17.0351, 5.05)
  point P36 (-17.0351, 20.05)
  vertical L5
  horizontal L6
  midpoint L3 L5
  midpoint L2 L6
  coincident L7 P17
  coincident L4 P17
  perpendicular L7 L14
  coincident L4 P18
  symmetric L6 P10 P24
  symmetric L6 P11 P25
  symmetric L6 P12 P26
  symmetric L6 P13 P27
  symmetric L6 P14 P22
  symmetric L6 P15 P21
  symmetric L6 P16 P19
  symmetric L6 P17 P23
  symmetric L6 P18 P20
  symmetric L5 P10 P42
  symmetric L5 P11 P43
  symmetric L5 P12 P44
  symmetric L5 P13 P45
  symmetric L5 P14 P40
  symmetric L5 P15 P39
  symmetric L5 P16 P37
  symmetric L5 P17 P41
  symmetric L5 P18 P38
  symmetric L5 P19 P28
  symmetric L5 P20 P29
  symmetric L5 P21 P30
  symmetric L5 P22 P31
  symmetric L5 P23 P32
  symmetric L5 P24 P33
  symmetric L5 P25 P34
  symmetric L5 P26 P35
  symmetric L5 P27 P36
  dimension "d332_3_2" distance P12 P13 = 15 (= "join_width2")
  dimension "d333_3_2" distance P10 P12 = 6 (= "join_depth * 2")
  dimension "d334_3_2" distance P10 P11 = 10 (= "join_width1")
  dimension "d336_3_2" distance P15 P16 = 14.9 (= "join_width2 - ( 2 * wall_clearance )")
  dimension "d337_3_2" distance P16 P18 = 5.95 (= "join_depth * 2 - wall_clearance")
  dimension "d338_3_2" distance P14 P17 = 0.05 (= "wall_clearance")
position "Position20"
sketch "Sketch4" plane through (0, 61.9879, 0) normal (0, 1, 0) x axis (1, 0, 0)
  line L1 (11.0351, -5.05) -> (100.8937, -5.05)
  line L2 (11.0351, -74.95) -> (11.0351, -5.05)
  line L3 (100.8937, -74.95) -> (11.0351, -74.95)
  line L4 (100.8937, -5.05) -> (100.8937, -74.95)
  line L5 (45.9644, -5.05) -> (45.9644, -12.415)
  line L6 (35.9644, -5.05) -> (35.9644, -12.415)
  line L7 (65.9644, -5.05) -> (65.9644, -12.423)
  line L8 (75.967, -5.05) -> (75.9644, -12.4248)
  line L9 (55.9644, 6.6527) -> (55.9644, -156.5527)
  circle C1 centre (15.9644, -20) radius 1.7
  circle C2 centre (95.9644, -60) radius 1.7
  circle C3 centre (95.9644, -20) radius 1.7
  circle C4 centre (15.9644, -60) radius 1.7
  arc A1 centre (40.9644, -12.415) radius 5 clockwise from (45.9644, -12.415) to (35.9644, -12.415)
  arc A2 centre (70.9644, -12.423) radius 5 clockwise from (75.9644, -12.4248) to (65.9644, -12.423)
  point P12 (45.9644, -5.05)
  point P14 (35.9644, -5.05)
  coincident L1 P12
  tangent L5 A1
  coincident L1 P14
  tangent L6 A1
  perpendicular L1 L6
  tangent A2 L8
  tangent L7 A2
  dimension "cable_hole_d_2" diameter A1 = 10
  dimension "d534" diameter A2 = 10
  dimension "d535" distance L7 L9 = 10
  dimension "d536" distance L5 L9 = 10
extrude "Extrude4" cut sketch "Sketch4" profile of A1 L1 L5 L6 L7 A2 L8 against normal blind 2 named "d517_2"
component_insert "Component Insert1"
sketch "Sketch1" plane through (0, 0, 5) normal (0, 0, 1) x axis (-1, 0, 0)
  line L1 (-98.9644, -53.9879) -> (-98.9644, -59.9879)
  line L2 (-92.9644, -53.9879) -> (-98.9644, -53.9879)
  line L3 (-92.9644, -59.9879) -> (-92.9644, -53.9879)
  line L4 (-98.9644, -59.9879) -> (-92.9644, -59.9879)
  line L5 (-12.9644, 60.0121) -> (-12.9644, 66.0121)
  line L6 (-18.9644, 60.0121) -> (-12.9644, 60.0121)
  line L7 (-18.9644, 66.0121) -> (-18.9644, 60.0121)
  line L8 (-12.9644, 66.0121) -> (-18.9644, 66.0121)
  line L9 (-45.9644, -51.9879) -> (-20.9644, -51.9879)
  line L10 (-40.9644, -54.9879) -> (-45.9644, -51.9879)
  line L11 (-70.9644, -54.9879) -> (-40.9644, -54.9879)
  line L12 (-65.9644, -51.9879) -> (-70.9644, -54.9879)
  line L13 (-90.9644, -51.9879) -> (-65.9644, -51.9879)
  line L14 (-90.9644, -6.9879) -> (-90.9644, -51.9879)
  line L15 (-93.9644, -11.9879) -> (-90.9644, -6.9879)
  line L16 (-93.9644, 18.0121) -> (-93.9644, -11.9879)
  line L17 (-90.9644, 13.0121) -> (-93.9644, 18.0121)
  line L18 (-90.9644, 58.0121) -> (-90.9644, 13.0121)
  line L19 (-65.9644, 58.0121) -> (-90.9644, 58.0121)
  line L20 (-70.9644, 61.0121) -> (-65.9644, 58.0121)
  line L21 (-40.9644, 61.0121) -> (-70.9644, 61.0121)
  line L22 (-45.9644, 58.0121) -> (-40.9644, 61.0121)
  line L23 (-20.9644, 58.0121) -> (-45.9644, 58.0121)
  line L24 (-20.9644, 13.0121) -> (-20.9644, 58.0121)
  line L25 (-17.9644, 18.0121) -> (-20.9644, 13.0121)
  line L26 (-17.9644, -11.9879) -> (-17.9644, 18.0121)
  line L27 (-20.9644, -6.9879) -> (-17.9644, -11.9879)
  line L28 (-20.9644, -51.9879) -> (-20.9644, -6.9879)
  line L29 (-12.9644, -53.9879) -> (-18.9644, -53.9879)
  line L30 (-12.9644, -59.9879) -> (-12.9644, -53.9879)
  line L31 (-18.9644, -59.9879) -> (-12.9644, -59.9879)
  line L32 (-18.9644, -53.9879) -> (-18.9644, -59.9879)
  line L33 (-98.9644, 60.0121) -> (-92.9644, 60.0121)
  line L34 (-98.9644, 66.0121) -> (-98.9644, 60.0121)
  line L35 (-92.9644, 66.0121) -> (-98.9644, 66.0121)
  line L36 (-92.9644, 60.0121) -> (-92.9644, 66.0121)
  line L37 (-10.9644, -6.9879) -> (-10.9644, -61.9879)
  line L38 (-13.9644, -11.9879) -> (-10.9644, -6.9879)
  line L39 (-13.9644, 18.0121) -> (-13.9644, -11.9879)
  line L40 (-10.9644, 13.0121) -> (-13.9644, 18.0121)
  line L41 (-10.9644, 68.0121) -> (-10.9644, 13.0121)
  line L42 (-45.9644, 68.0121) -> (-10.9644, 68.0121)
  line L43 (-40.9644, 65.0121) -> (-45.9644, 68.0121)
  line L44 (-70.9644, 65.0121) -> (-40.9644, 65.0121)
  line L45 (-65.9644, 68.0121) -> (-70.9644, 65.0121)
  line L46 (-100.9644, 68.0121) -> (-65.9644, 68.0121)
  line L47 (-100.9644, 13.0121) -> (-100.9644, 68.0121)
  line L48 (-97.9644, 18.0121) -> (-100.9644, 13.0121)
  line L49 (-97.9644, -11.9879) -> (-97.9644, 18.0121)
  line L50 (-100.9644, -6.9879) -> (-97.9644, -11.9879)
  line L51 (-100.9644, -61.9879) -> (-100.9644, -6.9879)
  line L52 (-65.9644, -61.9879) -> (-100.9644, -61.9879)
  line L53 (-70.9644, -58.9879) -> (-65.9644, -61.9879)
  line L54 (-40.9644, -58.9879) -> (-70.9644, -58.9879)
  line L55 (-45.9644, -61.9879) -> (-40.9644, -58.9879)
  line L56 (-10.9644, -61.9879) -> (-45.9644, -61.9879)
  line L57 (-100.9644, -61.9879) -> (-10.9644, -61.9879)
  line L58 (-99.9644, -60.9879) -> (-100.9644, -61.9879)
  line L59 (-91.9644, -60.9879) -> (-99.9644, -60.9879)
  line L60 (-91.9644, -59.9879) -> (-91.9644, -60.9879)
  line L61 (-19.9644, -59.9879) -> (-91.9644, -59.9879)
  line L62 (-19.9644, -60.9879) -> (-19.9644, -59.9879)
  line L63 (-11.9644, -60.9879) -> (-19.9644, -60.9879)
  line L64 (-10.9644, -61.9879) -> (-11.9644, -60.9879)
  line L65 (-99.9437, -61.0379) -> (-100.8937, -61.9879)
  line L66 (-91.9144, -61.0379) -> (-99.9437, -61.0379)
  line L67 (-91.9144, -60.0379) -> (-91.9144, -61.0379)
  line L68 (-20.0144, -60.0379) -> (-91.9144, -60.0379)
  line L69 (-20.0144, -61.0379) -> (-20.0144, -60.0379)
  line L70 (-11.9851, -61.0379) -> (-20.0144, -61.0379)
  line L71 (-11.0351, -61.9879) -> (-11.9851, -61.0379)
  circle C1 centre (-24.4644, 61.5121) radius 1.7
  circle C2 centre (-93.9644, 54.5121) radius 1.7
  circle C3 centre (-87.4644, -55.4879) radius 1.7
  circle C4 centre (-17.4644, -48.4879) radius 1.7
  circle C5 centre (-24.4644, -55.4879) radius 1.7
  circle C6 centre (-93.9644, -48.4879) radius 1.7
  circle C7 centre (-87.4644, 61.5121) radius 1.7
  circle C8 centre (-17.4644, 54.5121) radius 1.7
  point P46 (-10.9644, -61.9879)
  point P74 (-10.9644, -61.9879)
  point P61 (-100.9644, -61.9879)
  point P76 (-100.9644, -61.9879)
  point P68 (-99.9644, -60.9879)
  point P77 (-99.9644, -60.9879)
  point P69 (-91.9644, -60.9879)
  point P78 (-91.9644, -60.9879)
  point P70 (-91.9644, -59.9879)
  point P79 (-91.9644, -59.9879)
  point P71 (-19.9644, -59.9879)
  point P80 (-19.9644, -59.9879)
  point P72 (-19.9644, -60.9879)
  point P81 (-19.9644, -60.9879)
  point P73 (-11.9644, -60.9879)
  point P82 (-11.9644, -60.9879)
  point P89 (-11.0351, -61.9879)
  point P90 (-100.8937, -61.9879)
  point P75 (-100.9644, -61.9879)
  coincident P46 P74
  coincident P61 P76
  coincident P68 P77
  coincident P69 P78
  coincident P70 P79
  coincident P71 P80
  coincident P72 P81
  coincident P73 P82
  coincident L56 P89
  coincident L52 P90
  dimension "d228_4" distance L57 L70 = 0.95 (= "side_wall_thick1")
  dimension "d229_4" distance L57 L68 = 1.95 (= "side_wall_thick2")
  dimension "d230_4" distance L57 L66 = 0.95 (= "side_wall_thick1")
  dimension "d231_4" distance P74 P75 = 90 (= "plate_height")
  dimension "d232_4" distance L64 L71 = 0.05 (= "wall_clearance")
  dimension "d233_4" distance L58 L65 = 0.05 (= "wall_clearance")
  dimension "d234_4" angle L57 L58 = 45 (= "wall_rorner_angle")
  dimension "d235_4" distance P74 L69 = 9.05 (= "side_wall_col_length")
  dimension "d244_4" distance P75 L67 = 9.05 (= "side_wall_col_length")
extrude "Extrude1" new body sketch "Sketch1" profile of L52 L53 L55 L56 blind 69.9 (= "column_height - ( 2 * wall_clearance )") named "d217_4" from offset 0.05 (= "wall_clearance") named "d216_4"
sketch "Sketch2" plane through (0, 61.9879, 0) normal (0, 1, 0) x axis (-1, 0, 0)
  line L1 (-11.0351, 74.95) -> (-100.8937, 74.95)
  line L2 (-100.8937, 74.95) -> (-100.8937, 5.05)
  line L3 (-11.0351, 74.95) -> (-11.0351, 5.05)
  line L4 (-11.0351, 5.05) -> (-100.8937, 5.05)
  line L5 (-11.0351, 74.95) -> (-11.0351, 5.05)
  line L6 (-100.8937, 74.95) -> (-11.0351, 74.95)
  line L7 (-100.8937, 5.05) -> (-100.8937, 74.95)
  line L8 (-90.8937, 64.95) -> (-21.0351, 64.95)
  line L9 (-90.8937, 15.05) -> (-90.8937, 64.95)
  line L10 (-21.0351, 15.05) -> (-90.8937, 15.05)
  line L11 (-21.0351, 64.95) -> (-21.0351, 15.05)
  circle C1 centre (-95.9644, 60) radius 1.7
  circle C2 centre (-95.9644, 20) radius 1.7
  circle C3 centre (-15.9644, 20) radius 1.7
  circle C4 centre (-15.9644, 60) radius 1.7
hole "Hole1" HoleDepth 4 named "d220_1" HoleDiameter 3.4 named "d221_1" TipAngle 118 named "d222_1"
